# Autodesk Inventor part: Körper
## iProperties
Created: 2009-12
Part Number: Körper
Material: Stahl
Document SubType Name: Modeling
Designer: AEW
Mass: 5000 g
Surface Area: 40 cm^2
Volume: 12.5 cm^3
Density: 400 g/cm^3
Author: AEW
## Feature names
1. Extrusion1
